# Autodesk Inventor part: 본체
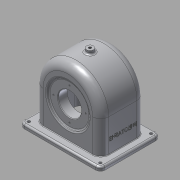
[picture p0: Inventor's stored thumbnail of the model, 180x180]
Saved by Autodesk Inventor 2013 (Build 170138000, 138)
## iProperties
Created: 2016-01
Part Number: 본체
Material: 알루미늄 6061
Document SubType Name: Modeling
Designer: dgall
Mass: 809.57 g
Surface Area: 999.65 cm^2
Volume: 298.734 cm^3
Density: 2.71 g/cm^3
Author: dgall
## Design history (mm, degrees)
sketch "스케치1"
  geometry: L1 (0, 0)-(140, 0); L2 (140, 0)-(140, 104); L3 (140, 104)-(0, 104); L4 (0, 104)-(0, 0); 1 further point
  constraints: 8 end point, 2 parallel, 1 coincident, 1 horizontal, 1 perpendicular
  dimensions: "d0" = 140 distance of L2.end L3.end; "d2" = 104 distance of L1.end L2.end
extrude "돌출1" new body sketch "스케치1" distance "d3" = 7; taper "d4" = 0 deg
sketch "스케치2"
  geometry: L1 (0, 0)-(140, 0) reference; L2 (140, 0)-(140, 104) reference; L3 (140, 104)-(0, 104) reference; L4 (0, 104)-(0, 0) reference; L5 (13, 90.5)-(127, 90.5); L6 (127, 90.5)-(127, 13.5); L7 (127, 13.5)-(13, 13.5); L8 (13, 13.5)-(13, 90.5); L9 (70, 104)-(70, 0); L10 (0, 52)-(140, 52); 2 further points
  constraints: 12 end point, 6 midpoint, 2 parallel, 2 point on line, 1 horizontal, 1 perpendicular
  dimensions: "d5" = 114 distance of L5.start L5.end; "d7" = 77 distance of L7.end L5.start
extrude "돌출2" join sketch "스케치2" distance "d8" = 114; taper "d9" = 0 deg
fillet "모깎기1" dims "d10" = 57
node "작업 평면1"
sketch "스케치3"
  geometry: L1 (127, 0)-(127, -7) reference; L2 (127, -7)-(-13, -7) reference; L3 (-13, -7)-(-13, 0) reference; L4 (-13, 0)-(0, 0) reference; L5 (0, 0)-(0, 57) reference; L6 (114, 57)-(114, 0) reference; L7 (114, 0)-(127, 0) reference; L8 (6, -7)-(6, 57); L9 (108, 57)-(108, -7); L10 (6, -7)-(108, -7); A1 r 57 centre (57, 57) between (114, 57) and (0, 57) reference; A2 r 51 centre (57, 57) between (108, 57) and (6, 57)
  constraints: 6 end point, 2 perpendicular, 2 point on circle, 2 point on line, 2 tangent, 1 centre point, 1 coincident
  dimensions: "d12" = 6 radial gap between concentric circles of A1 A2
extrude "돌출3" cut sketch "스케치3" distance "d13" = 67; taper "d14" = 0 deg
fillet "모깎기2" dims "d15" = 9
fillet "모깎기3" dims "d16" = 14
fillet "모깎기4" dims "d17" = 8
fillet "모깎기5" dims "d18" = 3
node "작업 평면2"
sketch "스케치4"
  geometry: L1 (-108, 49)-(-108, 0) reference; L2 (-99, -9)-(7, -9) reference; L3 (7, -9)-(7, -27.5) reference; L4 (7, -27.5)-(3, -27.5) reference; L5 (0, -24.5)-(0, -14) reference; L6 (0, -14)-(-100, -14) reference; L7 (-114, 0)-(-114, 49) reference; L8 (-100, 63)-(0, 63) reference; L9 (0, 63)-(0, 73.5) reference; L10 (3, 76.5)-(7, 76.5) reference; L11 (7, 76.5)-(7, 58) reference; L12 (7, 58)-(-99, 58) reference; L13 (-53, -14)-(-53, 63); L14 (-90.416, -14)-(-90.416, -9); L15 (-53, -9)-(-90.416, -9); L16 (-90.416, -14)-(-53, -14); A1 r 9 centre (-99, 49) between (-99, 58) and (-108, 49) reference; A2 r 9 centre (-99, 0) between (-108, 0) and (-99, -9) reference; A3 r 3 centre (3, -24.5) between (0, -24.5) and (3, -27.5) reference; A4 r 14 centre (-100, 0) between (-114, 0) and (-100, -14) reference; A5 r 14 centre (-100, 49) between (-100, 63) and (-114, 49) reference; A6 r 3 centre (3, 73.5) between (3, 76.5) and (0, 73.5) reference
  constraints: 8 end point, 6 point on line, 2 perpendicular, 1 collinear
  dimensions: "d19" = 60 distance between parallel lines of L11 L13
revolve "회전1" sketch "스케치4" stored, may be unused: angle "d24" = 90 deg
sketch "스케치5"
  geometry: L1 (7, -9)-(7, -27.5) reference; L2 (7, -27.5)-(3, -27.5) reference; L3 (0, -24.5)-(0, -14) reference; L4 (0, -14)-(-15.584, -14) reference; L5 (-15.584, -14)-(-15.584, -9) reference; L6 (-15.584, -9)-(7, -9) reference; L7 (-108, 49)-(-108, 0) reference; L8 (-99, -9)-(-90.416, -9) reference; L9 (-90.416, -9)-(-90.416, -14) reference; L10 (-90.416, -14)-(-100, -14) reference; L11 (-114, 0)-(-114, 49) reference; L12 (-100, 63)-(0, 63) reference; L13 (0, 63)-(0, 73.5) reference; L14 (3, 76.5)-(7, 76.5) reference; L15 (7, 76.5)-(7, 58) reference; L16 (7, 58)-(-99, 58) reference; L17 (-53, 63)-(-53, -14); L18 (-73, 5)-(-81, 5); L19 (-81, 5)-(-92.747, -9); L20 (-90.416, -14)-(-87.899, -11); L21 (-87.899, -11)-(-73, -11); L22 (-73, -11)-(-73, 5); A1 r 3 centre (3, -24.5) between (0, -24.5) and (3, -27.5) reference; A2 r 9 centre (-99, 49) between (-99, 58) and (-108, 49) reference; A3 r 9 centre (-99, 0) between (-108, 0) and (-99, -9) reference; A4 r 14 centre (-100, 0) between (-114, 0) and (-100, -14) reference; A5 r 14 centre (-100, 49) between (-100, 63) and (-114, 49) reference; A6 r 3 centre (3, 73.5) between (3, 76.5) and (0, 73.5) reference
  constraints: 12 end point, 3 perpendicular, 2 parallel, 2 point on line
  dimensions: "d25" = 60 distance between parallel lines of L15 L17; "d26" = 56 diameter of L18.end L17; "d28" = 50 deg angle of L18 L19; "d29" = 5 distance between parallel lines of L19 L20; "d30" = 3 distance between parallel lines of L10 L21; "d31" = 40 diameter of L22 L17
revolve "회전2" sketch "스케치5" stored, may be unused: angle "d32" = 90 deg
sketch "스케치6"
  geometry: L1 (85, 7)-(1, 7) reference; C1 r 31 at (43, -53); 1 further point
  constraints: 1 centre point
  dimensions: "d33" = 60 distance from line of L1 C1.centre; "d34" = 62 diameter of C1
extrude "돌출4" join sketch "스케치6" distance "d35" = 10; taper "d36" = 0 deg
sketch "스케치7"
  geometry: C1 r 31 at (0, 0) reference; C2 r 20 at (0, 0); 1 further point
  constraints: 1 centre point, 1 coincident
  dimensions: "d37" = 40 diameter of C2
extrude "돌출5" cut sketch "스케치7" stored distance "d39" = 10; taper "d40" = 0 deg
fillet "모깎기6" dims "d41" = 1
fillet "모깎기7" dims "d42" = 3
chamfer "모따기1" distance "d43" = 1; stored, may be unused: second distance "d44" = 2, angle "d45" = 45 deg
node "작업 평면3"
sketch "스케치8"
  geometry: L1 (13, 76.5)-(127, 76.5) reference; L2 (13, 76.5)-(13, 27.5) reference; L3 (127, 27.5)-(13, 27.5) reference; L4 (127, 27.5)-(127, 76.5) reference; L5 (28, 18.5)-(112, 18.5) reference; C1 r 6 at (70, 52); 2 further points
  constraints: 1 centre point, 1 midpoint, 1 vertical alignment
  dimensions: "d47" = 12 diameter of C1; "d49" = 33.5 distance from line of C1.centre L5
extrude "돌출6" join sketch "스케치8" stored distance "d50" = 10; taper "d51" = 0 deg
fillet "모깎기8" dims "d52" = 3
sketch "스케치9"
  geometry: C1 r 6 at (0, 0) reference; 1 further point
hole "구멍1" sketch "스케치9" at (0, 0) diameter "d53" = 4.459; stored, may be unused: countersink angle "d57" = 90 deg, drill point angle "d59" = 118 deg; dims "d54" = 100, "d55" = 4, "d56" = 2, "d58" = 8
sketch "스케치10" dims "d60" = 56
  geometry: C1 r 33.5 at (0, 0) reference; C2 r 21 at (0, 0) reference; 6 further points
  constraints: 2 vertical alignment, 1 coincident, 7 other
  dimensions: "d64" = 360 deg dimension on C1.centre point (0, 28) (derived)
hole "구멍2" sketch "스케치10" at (0, 28), (-28, 0), (0, -28), (28, 0) diameter "d66" = 2.459; stored, may be unused: countersink angle "d70" = 90 deg, drill point angle "d72" = 118 deg; dims "d67" = 7, "d68" = 4, "d69" = 2, "d71" = 9
sketch "스케치11" dims "d73" = 48
  geometry: C1 r 20 at (0, 0) reference; C2 r 31 at (0, 0) reference; 6 further points
  constraints: 2 vertical alignment, 1 coincident, 7 other
  dimensions: "d77" = 360 deg dimension on C1.centre point (0, -24) (derived)
hole "구멍3" sketch "스케치11" at (0, -24), (24, 0), (0, 24), (-24, 0) diameter "d79" = 2.459; stored, may be unused: countersink angle "d83" = 90 deg, drill point angle "d85" = 118 deg; dims "d80" = 6, "d81" = 4, "d82" = 2, "d84" = 8
fillet "모깎기9" dims "d86" = 3
chamfer "모따기2" distance "d87" = 1; stored, may be unused: second distance "d88" = 2, angle "d89" = 45 deg
sketch "스케치12"
  geometry: L1 (26.752, -0.387)-(26.752, 49.387); L2 (26.752, 49.387)-(41.248, 49.387); L3 (41.248, 49.387)-(41.248, -0.387); L4 (41.248, -0.387)-(26.752, -0.387); L5 (34, -0.387)-(34, 49.387); L6 (26.752, 24.5)-(41.248, 24.5); L7 (0, -14)-(56, -14) reference; L8 (64, -19.5)-(64, 68.5) reference; 1 further point
  constraints: 4 end point, 4 midpoint, 2 other
  dimensions: "d90" = 38.5 distance between parallel lines of L6 L7; "d91" = 30 distance between parallel lines of L8 L5
extrude "돌출7" join sketch "스케치12" distance "d92" = 0.5; taper "d93" = 0 deg
sketch "스케치13"
  geometry: C1 r 2.5 at (8, 96); C2 r 2.5 at (8, 8); C3 r 2.5 at (132, 8); C4 r 2.5 at (132, 96); A1 r 5 centre (132, 8) between (132, 3) and (137, 8) reference; A2 r 5 centre (132, 96) between (137, 96) and (132, 101) reference; A3 r 5 centre (8, 96) between (8, 101) and (3, 96) reference; A4 r 5 centre (8, 8) between (3, 8) and (8, 3) reference; 1 further point
  constraints: 4 centre point, 4 coincident, 3 equal radius
  dimensions: "d94" = 5 diameter of C1
extrude "돌출8" cut sketch "스케치13" stored distance "d97" = 0.5; taper "d98" = 0 deg
fillet "모깎기10" dims "d99" = 3
node "솔리드1"
node "투영된 루프1"
node "절단 모서리 투영1"
node "절단 모서리 투영2"
node "절단 모서리 투영3"
other parameters: "d11" = -5, "d46" = -127
